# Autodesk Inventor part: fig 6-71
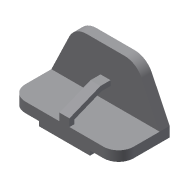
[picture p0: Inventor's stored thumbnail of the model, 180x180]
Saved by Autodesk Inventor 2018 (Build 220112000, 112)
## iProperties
Shininess: 77.0
Length Units: 11269
Angle Units: 11279
Time Units: 11290
Mass Units: 11283
Length Display Precision: 3
Angle Display Precision: 2
Created: 2001-12
Part Number: fig 6-71
Document SubType Name: Modeling
Designer: Renu Muthoo
Density: 1 g/cm^3
Material: Generic
Appearance: Default
Density: 0.0
Volumn: 0.0
Area: 0.0
PropertySet Name: Model Information
Control State: 0
Master: False
Checked Out: False
Author: Renu Muthoo
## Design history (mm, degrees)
sketch "Sketch2"
  geometry: L1 (-67.219, 19.116)-(148.781, 19.116); L2 (148.781, 19.116)-(148.781, -0.884); L3 (-67.219, -0.884)-(-67.219, 19.116); L4 (-10.219, -0.884)-(-10.219, -9.884); L5 (-10.219, -9.884)-(91.781, -9.884); L6 (91.781, -9.884)-(91.781, -0.884); L7 (148.781, -0.884)-(91.781, -0.884); L8 (-10.219, -0.884)-(-67.219, -0.884)
  constraints: 16 end point, 5 parallel, 4 perpendicular, 2 equal length, 1 horizontal
  dimensions: "d0" = 102 distance of L4.end L5.end; "d1" = 57 distance of L4.start L3.start; "d2" = 29 distance between parallel lines of L1 L5; "d3" = 20 distance of L1.end L2.end
extrude "Extrusion1" new body sketch "Sketch2" distance "d4" = 102; taper "d5" = 0 deg
sketch "Sketch3"
  geometry: L1 (67.219, -19.116)-(-148.781, -19.116) reference; L2 (67.219, -19.116)-(31.475, -93.564); L3 (-2.781, -115.116)-(-78.781, -115.116); L4 (-113.038, -93.564)-(-148.781, -19.116); A1 r 38 centre (-2.781, -77.116) between (-2.781, -115.116) and (31.475, -93.564); A2 r 38 centre (-78.781, -77.116) between (-113.038, -93.564) and (-78.781, -115.116)
  constraints: 6 end point, 4 point on circle, 4 tangent, 2 centre point, 1 equal length, 1 equal radius, 1 parallel
  dimensions: "d6" = 96 distance between parallel lines of L3 L1; "d7" = 38 radius of A1; "d8" = 76 distance of A2.centre A1.centre
extrude "Extrusion2" join sketch "Sketch3" distance "d9" = 20; taper "d10" = 0 deg
fillet "Fillet1" dims "d11" = 30
workplane "Work Plane1"
sketch "Sketch7"
  geometry: L1 (0, -82)-(-15, -82); L2 (-15, -82)-(-40, -20); L3 (-40, -20)-(-40, 0); L4 (0, -82)-(20, -82) reference; L5 (0, 0)-(-74.447, 0) reference
  constraints: 6 end point, 2 point on line, 1 horizontal, 1 perpendicular
  dimensions: "d32" = 20 distance of L2.end L3.end; "d33" = 15 distance of L1.start L1.end; "d34" = 40 distance of L5.start L3.end
feature "Rib4" sketch "Sketch7" dims "d55" = 10, "d56" = 20, "d57" = 0
body "Solid1"
other parameters: "d12" = -108
